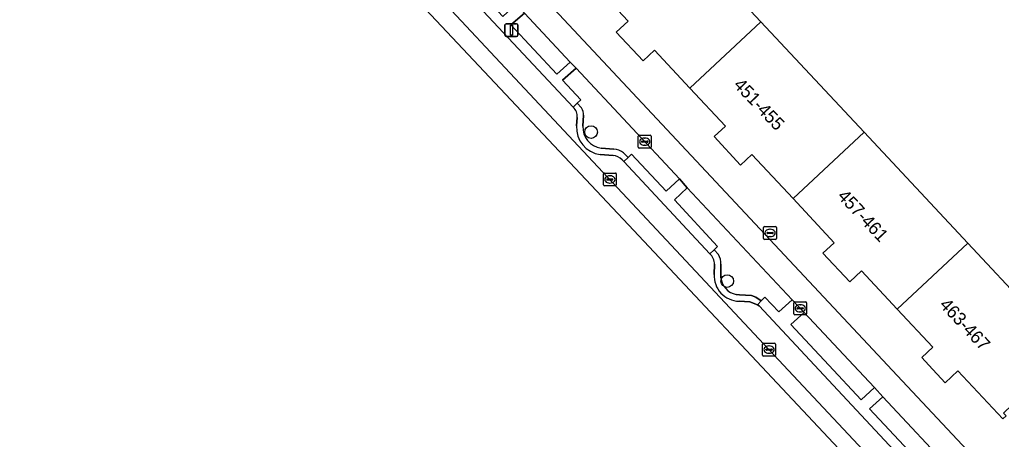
# Model space of a CAD drawing. Extents: x 163147 to 163550, y 380933 to 381639.
# Drawn here: x 163305.4 to 163381.5, y 380994.2 to 381026.8 of the extents above; entities that cross this region are included whole.
import ezdxf

# ---------------------------------------------------------------- set-up
doc = ezdxf.new("R2010")
doc.units = 0
for name, color, linetype in [('IMGEO_Berm_groen', 7, 'Continuous'), ('IMGEO_Berm_open', 7, 'Continuous'), ('IMGEO_Boom', 7, 'Continuous'), ('IMGEO_Brandkraan', 7, 'Continuous'), ('IMGEO_Erf', 7, 'Continuous'), ('IMGEO_Fietspad_gesloten', 7, 'Continuous'), ('IMGEO_Kolk', 7, 'Continuous'), ('IMGEO_Lichtmast', 7, 'Continuous'), ('IMGEO_Pand', 7, 'Continuous'), ('IMGEO_Pand_nummerreeks', 7, 'Continuous'), ('IMGEO_Parkeervlak_open', 7, 'Continuous'), ('IMGEO_Rijbaan_lokaal_gesloten', 7, 'Continuous'), ('IMGEO_Voetpad_open', 7, 'Continuous')]:
    doc.layers.add(name, color=color, linetype=linetype)

msp = doc.modelspace()

# ---------------------------------------------------------------- linework, layer by layer
at = {"layer": 'IMGEO_Berm_groen'}
for points in [[(163344.515, 381027.25), (163343.471, 381026.337), (163347.031, 381022.522), (163348.067, 381023.459)], [(163366.186, 381004.068), (163365.152, 381003.133), (163368.09, 381000), (163370.609, 380997.315), (163371.64, 380998.255), (163370.003, 381000)]]:
    msp.add_lwpolyline(points, close=True, dxfattribs=at)
for points in [[(163348.514, 381022.981), (163347.451, 381022.072), (163348.877, 381020.544), (163348.609, 381020.284), (163348.944, 381019.912)], [(163352.197, 381016.444), (163352.54, 381016.081), (163352.796, 381016.322), (163355.492, 381013.462), (163356.522, 381014.433), (163348.514, 381022.981)], [(163349.1, 381019.342), (163349.046, 381018.511)], [(163350.447, 381016.8), (163351.44, 381016.727)], [(163357.127, 381013.723), (163356.129, 381012.803), (163359.476, 381009.183), (163359.204, 381008.929), (163359.545, 381008.563)], [(163360.912, 381005.472), (163361.172, 381005.445), (163362.094, 381005.4), (163362.434, 381005.265), (163362.851, 381004.975), (163363.146, 381005.271), (163364.22, 381004.126), (163365.262, 381005.053), (163357.127, 381013.723)], [(163359.734, 381007.809), (163359.717, 381007.025), (163359.723, 381006.761)], [(163377.885, 380991.559), (163372.278, 380997.54), (163371.247, 380996.624), (163377.337, 380990.096), (163377.049, 380989.826), (163377.391, 380989.461)]]:
    msp.add_lwpolyline(points, dxfattribs=at)
for centre, radius, start, end in [((163347.951, 381019.334), 1.149, 0.40759, 30.20469), ((163350.658, 381018.402), 1.615, 176.11846, 262.50411), ((163351.296, 381015.188), 1.546, 54.34959, 84.65449), ((163358.284, 381007.846), 1.451, 358.53056, 29.61343), ((163361.177, 381006.909), 1.461, 185.8214, 259.55675)]:
    msp.add_arc(centre, radius, start, end, dxfattribs=at)
at = {"layer": 'IMGEO_Berm_open'}
for points in [[(163348.944, 381019.912), (163348.609, 381020.284), (163348.277, 381019.96)], [(163348.592, 381019.175), (163348.546, 381018.522)], [(163349.046, 381018.511), (163349.1, 381019.342)], [(163351.44, 381016.727), (163350.447, 381016.8)], [(163350.375, 381016.304), (163351.381, 381016.23)], [(163352.074, 381015.9), (163352.202, 381015.762), (163352.54, 381016.081), (163352.197, 381016.444)], [(163359.545, 381008.563), (163359.204, 381008.929), (163358.873, 381008.62)], [(163359.234, 381007.802), (163359.217, 381007.025)], [(163359.723, 381006.761), (163359.717, 381007.025), (163359.734, 381007.809)], [(163361.134, 381004.946), (163361.986, 381004.905), (163362.555, 381004.678), (163362.851, 381004.975), (163362.434, 381005.265), (163362.094, 381005.4), (163361.172, 381005.445), (163360.912, 381005.472)]]:
    msp.add_lwpolyline(points, dxfattribs=at)
for centre, radius, start, end in [((163347.735, 381019.287), 0.864, 352.55793, 51.17067), ((163347.951, 381019.334), 1.149, 0.40759, 30.20469), ((163350.655, 381018.398), 2.113, 176.63538, 262.38375), ((163350.658, 381018.402), 1.615, 176.11846, 262.50411), ((163351.296, 381015.188), 1.546, 54.34959, 84.65449), ((163351.275, 381015.114), 1.121, 44.51152, 84.56179), ((163358.184, 381007.827), 1.051, 358.62964, 48.99605), ((163358.284, 381007.846), 1.451, 358.53056, 29.61343), ((163361.178, 381006.91), 1.964, 176.63559, 268.72134), ((163361.177, 381006.909), 1.461, 185.8214, 259.55675)]:
    msp.add_arc(centre, radius, start, end, dxfattribs=at)
at = {"layer": 'IMGEO_Boom'}
for centre in [(163349.676, 381018.045), (163360.22, 381006.503)]:
    msp.add_circle(centre, 0.489, dxfattribs=at)
at = {"layer": 'IMGEO_Brandkraan'}
for p, q in [((163363.043, 381009.81), (163363.043, 381010.662)), ((163363.118, 381010.736), (163363.97, 381010.736)), ((163363.531, 381010.516), (163363.556, 381010.516)), ((163364.044, 381010.662), (163364.044, 381009.81)), ((163363.97, 381009.736), (163363.118, 381009.736)), ((163363.302, 381010.23), (163363.302, 381010.242)), ((163363.74, 381010.193), (163363.342, 381010.193)), ((163363.345, 381010.279), (163363.743, 381010.279)), ((163363.554, 381009.956), (163363.529, 381009.956)), ((163363.786, 381010.242), (163363.786, 381010.23))]:
    msp.add_line(p, q, dxfattribs=at)
for points in [[(163363.043, 381009.81), (163363.043, 381010.662)], [(163363.118, 381010.736), (163363.97, 381010.736)], [(163364.044, 381010.662), (163364.044, 381009.81)], [(163363.97, 381009.736), (163363.118, 381009.736)]]:
    msp.add_lwpolyline(points, dxfattribs=at)
for centre, radius, start, end in [((163363.12, 381010.66), 0.0765, 91.55205, 178.44795), ((163363.12, 381010.66), 0.0765, 91.55205, 178.44795), ((163363.968, 381010.66), 0.0765, 1.55205, 88.44795), ((163363.968, 381010.66), 0.0765, 1.55205, 88.44795), ((163363.12, 381009.812), 0.0765, 181.55205, 268.44795), ((163363.12, 381009.812), 0.0765, 181.55205, 268.44795), ((163363.342, 381010.239), 0.0403, 85.87752, 175.75265), ((163363.339, 381010.229), 0.0366, 178.93798, 274.71019), ((163363.743, 381010.236), 0.043, 264.86636, 352.45326), ((163363.747, 381010.241), 0.0386, 1.73085, 96.63898), ((163363.968, 381009.812), 0.0765, 271.55205, 358.44795), ((163363.968, 381009.812), 0.0765, 271.55205, 358.44795)]:
    msp.add_arc(centre, radius, start, end, dxfattribs=at)
for centre, major_axis, ratio, start_param, end_param in [((163363.53, 381010.236), (-0.387, 0.002), 0.722429, 4.712389, 7.853982), ((163363.555, 381010.236), (-0.39, 0.002), 0.717154, 1.570796, 4.712389)]:
    msp.add_ellipse(centre, major_axis=major_axis, ratio=ratio, start_param=start_param, end_param=end_param, dxfattribs=at)
at = {"layer": 'IMGEO_Erf'}
msp.add_lwpolyline([(163354.856, 381035.112), (163362.831, 381026.582), (163370.824, 381018.034), (163378.849, 381009.451), (163383.684, 381004.28)], dxfattribs=at)
at = {"layer": 'IMGEO_Fietspad_gesloten'}
for points in [[(163431.634, 380936.983), (163426.381, 380942.59), (163389.734, 380981.756), (163386.168, 380985.564), (163372.648, 381000), (163319.829, 381056.397), (163310.14, 381066.773), (163306.558, 381070.608), (163278.278, 381100.892), (163188.415, 381197.241)], [(163300.254, 381074.541), (163308.689, 381065.5), (163311.897, 381062.058), (163312.543, 381061.369), (163314.772, 381058.98), (163315.706, 381057.986), (163318.395, 381055.109), (163325.365, 381047.696), (163326.013, 381046.997), (163337.548, 381034.692), (163338.375, 381033.79), (163343.87, 381027.948), (163344.515, 381027.25), (163348.067, 381023.459), (163348.514, 381022.981), (163356.522, 381014.433), (163357.127, 381013.723), (163365.262, 381005.053), (163366.186, 381004.068), (163370.003, 381000), (163371.64, 380998.255), (163372.278, 380997.54), (163377.885, 380991.559)]]:
    msp.add_lwpolyline(points, dxfattribs=at)
at = {"layer": 'IMGEO_Kolk'}
for p, q in [((163353.333, 381016.875), (163353.333, 381017.727)), ((163353.408, 381017.801), (163354.26, 381017.801)), ((163353.592, 381017.295), (163353.592, 381017.307)), ((163353.635, 381017.344), (163354.033, 381017.344)), ((163353.821, 381017.581), (163353.846, 381017.581)), ((163354.076, 381017.307), (163354.076, 381017.295)), ((163354.334, 381017.727), (163354.334, 381016.875)), ((163354.26, 381016.801), (163353.408, 381016.801)), ((163354.03, 381017.258), (163353.632, 381017.258)), ((163353.844, 381017.021), (163353.819, 381017.021)), ((163350.629, 381013.947), (163350.629, 381014.799)), ((163350.704, 381014.873), (163351.556, 381014.873)), ((163350.888, 381014.367), (163350.888, 381014.379)), ((163351.326, 381014.33), (163350.928, 381014.33)), ((163350.931, 381014.416), (163351.329, 381014.416)), ((163351.117, 381014.653), (163351.142, 381014.653)), ((163351.372, 381014.379), (163351.372, 381014.367)), ((163351.63, 381014.799), (163351.63, 381013.947)), ((163351.556, 381013.873), (163350.704, 381013.873)), ((163351.14, 381014.093), (163351.115, 381014.093)), ((163365.373, 381003.972), (163365.373, 381004.824)), ((163365.448, 381004.898), (163366.3, 381004.898)), ((163365.632, 381004.392), (163365.632, 381004.404)), ((163365.675, 381004.441), (163366.073, 381004.441)), ((163365.861, 381004.678), (163365.886, 381004.678)), ((163366.116, 381004.404), (163366.116, 381004.392)), ((163366.374, 381004.824), (163366.374, 381003.972)), ((163366.3, 381003.898), (163365.448, 381003.898)), ((163366.07, 381004.355), (163365.672, 381004.355)), ((163365.884, 381004.118), (163365.859, 381004.118)), ((163362.965, 381000.773), (163362.965, 381001.625)), ((163363.04, 381001.699), (163363.892, 381001.699)), ((163363.453, 381001.479), (163363.478, 381001.479)), ((163363.966, 381001.625), (163363.966, 381000.773)), ((163363.892, 381000.699), (163363.04, 381000.699)), ((163363.224, 381001.193), (163363.224, 381001.205)), ((163363.662, 381001.156), (163363.264, 381001.156)), ((163363.267, 381001.242), (163363.665, 381001.242)), ((163363.476, 381000.919), (163363.451, 381000.919)), ((163363.708, 381001.205), (163363.708, 381001.193))]:
    msp.add_line(p, q, dxfattribs=at)
for points in [[(163353.333, 381016.875), (163353.333, 381017.727)], [(163353.408, 381017.801), (163354.26, 381017.801)], [(163354.334, 381017.727), (163354.334, 381016.875)], [(163354.26, 381016.801), (163353.408, 381016.801)], [(163350.629, 381013.947), (163350.629, 381014.799)], [(163350.704, 381014.873), (163351.556, 381014.873)], [(163351.63, 381014.799), (163351.63, 381013.947)], [(163351.556, 381013.873), (163350.704, 381013.873)], [(163365.373, 381003.972), (163365.373, 381004.824)], [(163365.448, 381004.898), (163366.3, 381004.898)], [(163366.374, 381004.824), (163366.374, 381003.972)], [(163366.3, 381003.898), (163365.448, 381003.898)], [(163362.965, 381000.773), (163362.965, 381001.625)], [(163363.04, 381001.699), (163363.892, 381001.699)], [(163363.966, 381001.625), (163363.966, 381000.773)], [(163363.892, 381000.699), (163363.04, 381000.699)]]:
    msp.add_lwpolyline(points, dxfattribs=at)
for centre, radius, start, end in [((163353.41, 381017.725), 0.0765, 91.55205, 178.44795), ((163353.41, 381017.725), 0.0765, 91.55205, 178.44795), ((163353.632, 381017.304), 0.0403, 85.87752, 175.75265), ((163353.629, 381017.294), 0.0366, 178.93798, 274.71019), ((163354.033, 381017.301), 0.043, 264.86636, 352.45326), ((163354.037, 381017.306), 0.0386, 1.73085, 96.63898), ((163354.258, 381017.725), 0.0765, 1.55205, 88.44795), ((163354.258, 381017.725), 0.0765, 1.55205, 88.44795), ((163353.41, 381016.877), 0.0765, 181.55205, 268.44795), ((163353.41, 381016.877), 0.0765, 181.55205, 268.44795), ((163354.258, 381016.877), 0.0765, 271.55205, 358.44795), ((163354.258, 381016.877), 0.0765, 271.55205, 358.44795), ((163350.706, 381014.797), 0.0765, 91.55205, 178.44795), ((163350.706, 381014.797), 0.0765, 91.55205, 178.44795), ((163350.928, 381014.376), 0.0403, 85.87752, 175.75265), ((163350.925, 381014.366), 0.0366, 178.93798, 274.71019), ((163351.329, 381014.373), 0.043, 264.86636, 352.45326), ((163351.333, 381014.378), 0.0386, 1.73085, 96.63898), ((163351.554, 381014.797), 0.0765, 1.55205, 88.44795), ((163351.554, 381014.797), 0.0765, 1.55205, 88.44795), ((163350.706, 381013.949), 0.0765, 181.55205, 268.44795), ((163350.706, 381013.949), 0.0765, 181.55205, 268.44795), ((163351.554, 381013.949), 0.0765, 271.55205, 358.44795), ((163351.554, 381013.949), 0.0765, 271.55205, 358.44795), ((163365.45, 381004.822), 0.0765, 91.55205, 178.44795), ((163365.45, 381004.822), 0.0765, 91.55205, 178.44795), ((163365.672, 381004.401), 0.0403, 85.87752, 175.75265), ((163365.669, 381004.391), 0.0366, 178.93798, 274.71019), ((163366.073, 381004.398), 0.043, 264.86636, 352.45326), ((163366.077, 381004.403), 0.0386, 1.73085, 96.63898), ((163366.298, 381004.822), 0.0765, 1.55205, 88.44795), ((163366.298, 381004.822), 0.0765, 1.55205, 88.44795), ((163365.45, 381003.974), 0.0765, 181.55205, 268.44795), ((163365.45, 381003.974), 0.0765, 181.55205, 268.44795), ((163366.298, 381003.974), 0.0765, 271.55205, 358.44795), ((163366.298, 381003.974), 0.0765, 271.55205, 358.44795), ((163363.042, 381001.623), 0.0765, 91.55205, 178.44795), ((163363.042, 381001.623), 0.0765, 91.55205, 178.44795), ((163363.89, 381001.623), 0.0765, 1.55205, 88.44795), ((163363.89, 381001.623), 0.0765, 1.55205, 88.44795), ((163363.042, 381000.775), 0.0765, 181.55205, 268.44795), ((163363.042, 381000.775), 0.0765, 181.55205, 268.44795), ((163363.264, 381001.202), 0.0403, 85.87752, 175.75265), ((163363.261, 381001.192), 0.0366, 178.93798, 274.71019), ((163363.665, 381001.199), 0.043, 264.86636, 352.45326), ((163363.669, 381001.204), 0.0386, 1.73085, 96.63898), ((163363.89, 381000.775), 0.0765, 271.55205, 358.44795), ((163363.89, 381000.775), 0.0765, 271.55205, 358.44795)]:
    msp.add_arc(centre, radius, start, end, dxfattribs=at)
for centre, major_axis, ratio, start_param, end_param in [((163353.82, 381017.301), (-0.387, 0.002), 0.722429, 4.712389, 7.853982), ((163353.845, 381017.301), (-0.39, 0.002), 0.717154, 1.570796, 4.712389), ((163351.116, 381014.373), (-0.387, 0.002), 0.722429, 4.712389, 7.853982), ((163351.141, 381014.373), (-0.39, 0.002), 0.717154, 1.570796, 4.712389), ((163365.86, 381004.398), (-0.387, 0.002), 0.722429, 4.712389, 7.853982), ((163365.885, 381004.398), (-0.39, 0.002), 0.717154, 1.570796, 4.712389), ((163363.452, 381001.199), (-0.387, 0.002), 0.722429, 4.712389, 7.853982), ((163363.477, 381001.199), (-0.39, 0.002), 0.717154, 1.570796, 4.712389)]:
    msp.add_ellipse(centre, major_axis=major_axis, ratio=ratio, start_param=start_param, end_param=end_param, dxfattribs=at)
at = {"layer": 'IMGEO_Lichtmast'}
for p, q in [((163343.106, 381026.436), (163343.896, 381026.436)), ((163343.896, 381026.436), (163343.106, 381026.436)), ((163343.006, 381025.536), (163343.006, 381026.336)), ((163343.006, 381026.336), (163343.006, 381025.536)), ((163343.996, 381026.336), (163343.996, 381025.536)), ((163343.996, 381025.536), (163343.996, 381026.336)), ((163343.896, 381025.436), (163343.106, 381025.436)), ((163343.106, 381025.436), (163343.896, 381025.436))]:
    msp.add_line(p, q, dxfattribs=at)
msp.add_lwpolyline([(163343.426, 381026.311), (163343.576, 381026.311), (163343.576, 381025.561), (163343.426, 381025.561), (163343.426, 381026.311)], dxfattribs=at)
for centre, start, end in [((163343.106, 381026.336), 90, 180), ((163343.106, 381026.336), 90, 180), ((163343.896, 381026.336), 0, 90), ((163343.896, 381026.336), 360, 90), ((163343.106, 381025.536), 180, 270), ((163343.106, 381025.536), 180, 270), ((163343.896, 381025.536), 270, 0), ((163343.896, 381025.536), 270, 0)]:
    msp.add_arc(centre, 0.1, start, end, dxfattribs=at)
at = {"layer": 'IMGEO_Pand'}
for points in [[(163349.398, 381030.01), (163352.55, 381026.639), (163351.626, 381025.775), (163353.708, 381023.549), (163354.593, 381024.376), (163357.335, 381021.443), (163362.831, 381026.582), (163354.856, 381035.112)], [(163370.824, 381018.034), (163362.831, 381026.582), (163357.335, 381021.443), (163360.078, 381018.51), (163359.2, 381017.689), (163361.256, 381015.491), (163362.128, 381016.307), (163365.322, 381012.89)], [(163378.849, 381009.451), (163370.824, 381018.034), (163365.322, 381012.89), (163368.516, 381009.474), (163367.641, 381008.656), (163369.708, 381006.445), (163370.611, 381007.289), (163373.376, 381004.332)], [(163378.849, 381009.451), (163373.376, 381004.332), (163376.14, 381001.376), (163375.291, 381000.583), (163375.832, 381000.005), (163377.095, 380998.622), (163378.075, 380999.546), (163381.571, 380995.838), (163381.819, 380996.072), (163381.618, 380996.286), (163383.625, 380998.178), (163383.829, 380997.961), (163384.694, 380998.777), (163384.486, 380998.997), (163385.623, 381000), (163386.434, 381000.715), (163386.787, 381000.337), (163387.099, 381000.628), (163383.684, 381004.28)]]:
    msp.add_lwpolyline(points, close=True, dxfattribs=at)
at = {"layer": 'IMGEO_Parkeervlak_open'}
for points in [[(163317.29, 381050.513), (163364.587, 381000), (163377.34, 380986.38)], [(163348.277, 381019.96), (163330.88, 381038.568)], [(163348.546, 381018.522), (163348.592, 381019.175)], [(163351.381, 381016.23), (163350.375, 381016.304)], [(163358.873, 381008.62), (163352.202, 381015.762), (163352.074, 381015.9)], [(163359.217, 381007.025), (163359.234, 381007.802)], [(163376.734, 380989.53), (163366.971, 381000), (163362.701, 381004.578), (163362.555, 381004.678), (163361.986, 381004.905), (163361.134, 381004.946)]]:
    msp.add_lwpolyline(points, dxfattribs=at)
for centre, radius, start, end in [((163347.735, 381019.287), 0.864, 352.55793, 51.17067), ((163350.655, 381018.398), 2.113, 176.63538, 262.38375), ((163351.275, 381015.114), 1.121, 44.51152, 84.56179), ((163358.184, 381007.827), 1.051, 358.62964, 48.99605), ((163361.178, 381006.91), 1.964, 176.63559, 268.72134)]:
    msp.add_arc(centre, radius, start, end, dxfattribs=at)
at = {"layer": 'IMGEO_Rijbaan_lokaal_gesloten'}
msp.add_lwpolyline([(163224.239, 381147.157), (163352.566, 381010.865), (163426.034, 380932.648), (163426.972, 380933.374), (163422.924, 380937.67), (163422.094, 380938.572), (163420.941, 380939.796), (163409.396, 380952.093), (163401.186, 380960.886), (163388.886, 380973.983), (163385.374, 380977.709), (163378.305, 380985.296), (163377.772, 380985.918), (163377.34, 380986.38), (163364.587, 381000), (163317.29, 381050.513), (163315.186, 381052.783), (163313.128, 381055.003), (163312.964, 381055.179), (163310.91, 381057.369), (163306.317, 381062.264), (163305.819, 381062.795), (163299.374, 381069.695)], dxfattribs=at)
at = {"layer": 'IMGEO_Voetpad_open'}
for points in [[(163319.829, 381056.397), (163372.648, 381000), (163386.168, 380985.564)], [(163381.571, 380995.838), (163378.075, 380999.546), (163377.095, 380998.622), (163375.832, 381000.005), (163375.291, 381000.583), (163376.14, 381001.376), (163373.376, 381004.332), (163370.611, 381007.289), (163369.708, 381006.445), (163367.641, 381008.656), (163368.516, 381009.474), (163365.322, 381012.89), (163362.128, 381016.307), (163361.256, 381015.491), (163359.2, 381017.689), (163360.078, 381018.51), (163357.335, 381021.443), (163354.593, 381024.376), (163353.708, 381023.549), (163351.626, 381025.775), (163352.55, 381026.639), (163349.398, 381030.01)]]:
    msp.add_lwpolyline(points, dxfattribs=at)
for points in [[(163344.515, 381027.25), (163343.87, 381027.948), (163342.851, 381027.002), (163337.38, 381032.862), (163338.375, 381033.79), (163337.548, 381034.692), (163336.526, 381033.765), (163331.547, 381039.08), (163331.213, 381038.824), (163330.88, 381038.568), (163348.277, 381019.96), (163348.609, 381020.284), (163348.877, 381020.544), (163347.451, 381022.072), (163348.514, 381022.981), (163348.067, 381023.459), (163347.031, 381022.522), (163343.471, 381026.337)], [(163357.127, 381013.723), (163356.522, 381014.433), (163355.492, 381013.462), (163352.796, 381016.322), (163352.54, 381016.081), (163352.202, 381015.762), (163358.873, 381008.62), (163359.204, 381008.929), (163359.476, 381009.183), (163356.129, 381012.803)], [(163371.247, 380996.624), (163372.278, 380997.54), (163371.64, 380998.255), (163370.609, 380997.315), (163368.09, 381000), (163365.152, 381003.133), (163366.186, 381004.068), (163365.262, 381005.053), (163364.22, 381004.126), (163363.146, 381005.271), (163362.851, 381004.975), (163362.555, 381004.678), (163362.701, 381004.578), (163366.971, 381000), (163376.734, 380989.53), (163377.049, 380989.826), (163377.337, 380990.096)]]:
    msp.add_lwpolyline(points, close=True, dxfattribs=at)

# ---------------------------------------------------------------- texts
at = {"layer": 'IMGEO_Pand_nummerreeks'}
for s, rotation, p in [('451-455', 313.52538, (163360.646, 381021.64)), ('457-461', 313.07196, (163368.705, 381013.031)), ('463-467', 313.07196, (163376.604, 381004.61))]:
    msp.add_text(s, height=1, rotation=rotation, dxfattribs=at).set_placement(p)

doc.saveas('drawing.dxf')
